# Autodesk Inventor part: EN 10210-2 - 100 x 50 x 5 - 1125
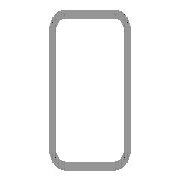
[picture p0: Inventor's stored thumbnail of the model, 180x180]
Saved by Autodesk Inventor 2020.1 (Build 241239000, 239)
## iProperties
Created: 2019-01
Part Number: EN 10210-2 - 100 x 50 x 5 - 1125
Material: Stahl, weich
Description: Rohrleitung
Document SubType Name: Modeling
Standard: DIN
Designer: lutzd
Standard Revision: 2006-07
Standards Organization: DIN
Language: de-DE
Size Designation: 100 x 50 x 5
Categories: <MemberInstance><Categories><Category DisplayName="Profile" InternalName="089c4875-fa83-4c05-b084-43b9cc11f5ed" Mnemonic="GRDR"><CategoryParameter DisplayName="
Stock Number: 100 x 50 x 5
Mass: 12126.8 g
Surface Area: 6086.04 cm^2
Volume: 1544.82 cm^3
Density: 7.85 g/cm^3
Appearance: Semi-Polished(8)
_CCFamilyMember: 159
_CCFamilyDisplayName: DIN EN 10210-2 (USAS B17.1 rechteckig) - Rohrleitung — In Klammern angegebene Größen wurden aufgehoben
_FrameMemberDoc: Frame Member File
_Version: 15.0.0
_GetPNFromCC: 1
G_W: 50,000 mm
G_H: 100,000 mm
+731142F7-15F3-4859-9C6F-473B57E24D15+SCHNITTDETAIL3: Schnittwinkel 90,00 grd
G_L: 1125,000 mm
DocNumber: ADSK-014252
Folder: .
Dimensions: 50x100x1125 mm
Mass: 12,127 kg
IsCustomPart: 1
Title: Profil-Bauteil
Author: lutzd
Revision Number: -
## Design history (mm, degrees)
node "Startebene"
node "Endebene"
sketch "Skizze"
  geometry: L1 (-25, -42.5)-(-25, 42.5); L2 (-17.5, 50)-(17.5, 50); L3 (25, 42.5)-(25, -42.5); L4 (17.5, -50)-(-17.5, -50); L5 (-15, 45)-(15, 45); L6 (20, 40)-(20, -40); L7 (15, -45)-(-15, -45); L8 (-20, -40)-(-20, 40); L9 (0, 72.175)-(0, -72.175) reference; L10 (-37.175, 0)-(37.175, 0) reference; A1 r 7.5 centre (-17.5, -42.5) between (-25, -42.5) and (-17.5, -50); A2 r 7.5 centre (-17.5, 42.5) between (-17.5, 50) and (-25, 42.5); A3 r 7.5 centre (17.5, 42.5) between (25, 42.5) and (17.5, 50); A4 r 7.5 centre (17.5, -42.5) between (17.5, -50) and (25, -42.5); A5 r 5 centre (-15, -40) between (-20, -40) and (-15, -45); A6 r 5 centre (-15, 40) between (-15, 45) and (-20, 40); A7 r 5 centre (15, 40) between (20, 40) and (15, 45); A8 r 5 centre (15, -40) between (15, -45) and (20, -40)
  constraints: 16 end point, 16 point on circle, 16 tangent, 8 centre point, 6 equal radius, 4 parallel, 2 perpendicular, 2 other
  dimensions: "d7" = 7.5 radius of A1 (= G_IR); "d10" = 100 distance between parallel lines of L2 L4 (= G_H); "d11" = 50 distance between parallel lines of L1 L3 (= G_W); "d12" = 5 distance between parallel lines of L3 L6 (= G_T); "d15" = 50 distance between parallel lines of L2 L10 (= 0.5 x d10); "d16" = 25 distance between parallel lines of L9 L3 (= 0.5 x d11); "d19" = 5 radius of A5 (= G_T); "d20" = 5 distance between parallel lines of L4 L7 (= G_T)
extrude "Körper" new body sketch "Skizze" stored distance "d3" = 1125 (= G_L); taper "d4" = 0 deg
node "Driven Length"
  sketch "Sketch3"
    geometry: L1 (0, 0)-(10, 0) reference
    constraints: 2 end point, 1 horizontal
  workplane "Work Plane3"
  sketch "Sketch4"
    geometry: L1 (-2, -566)-(12, -566) reference; L2 (-2, 559)-(12, 559) reference
    dimensions: "d18" = 1125 distance between parallel lines of L1 L2 (derived)
workplane "Arbeitsebene6"
feature "Trennen3"
body "Solid1"
other parameters: "G_W" = 50 [user parameter; used in 1 equation term], "G_H" = 100 [user parameter; used in 1 equation term], "G_T" = 5 [user parameter; used in 3 equation terms], "G_IR" = 7.5 [user parameter; used in 1 equation term], "G_L" = 1125 (= d18) [user parameter; used in 1 equation term], "G_OFFSET_START" = 566 [user parameter; used in 1 equation term], "G_OFFSET_END" = 0 [user parameter; used in 1 equation term], "d13" = -566 (= -G_OFFSET_START), "d14" = 559 (= G_OFFSET_END + B_L), "B_L" = 559 [user parameter; used in 1 equation term], "d17" = 90 deg
